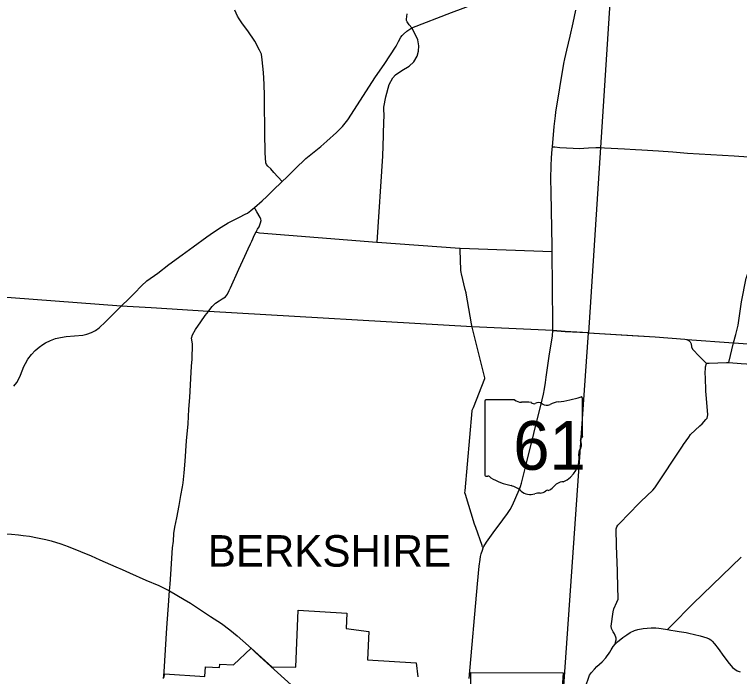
# Model space of a CAD drawing. Extents: x 1729596 to 1925846, y 659247 to 911751.
# Drawn here: x 1855559 to 1876281, y 821273 to 840189 of the extents above; entities that cross this region are included whole.
import ezdxf

# ---------------------------------------------------------------- set-up
doc = ezdxf.new("R2010")
doc.units = 0
for name, color, linetype in [('GM_X_Corporation', 7, 'Continuous'), ('GM_X_County_Road', 7, 'Continuous'), ('GM_X_State_Route', 7, 'Continuous'), ('GM_X_State_Shield', 7, 'Continuous'), ('GM_X_Township', 7, 'Continuous'), ('GM_X_Township_Road', 7, 'Continuous'), ('GM_X_Township_Text', 7, 'Continuous'), ('GM_X_US_Route', 7, 'Continuous')]:
    doc.layers.add(name, color=color, linetype=linetype)

msp = doc.modelspace()

# ---------------------------------------------------------------- linework, layer by layer
at = {"layer": 'GM_X_Corporation'}
for points in [[(1859841, 821244), (1859848, 821345), (1860999, 821277), (1861021, 821551), (1861422, 821527), (1861430, 821628), (1861816, 821605), (1862321, 822084), (1862912, 821546), (1863596, 821544), (1863668, 823164), (1865058, 823080), (1865034, 822645), (1865687, 822560), (1865651, 821750), (1867041, 821665), (1867085, 821260)], [(1868600, 820997), (1868600, 821384), (1871245, 821376), (1871152, 820118)]]:
    msp.add_lwpolyline(points, dxfattribs=at)
at = {"layer": 'GM_X_County_Road'}
for points in [[(1863210, 835416), (1863210, 835416), (1862967, 835675), (1862884, 835775), (1862803, 835851), (1862761, 835902), (1862743, 835950), (1862731, 836098), (1862723, 836235), (1862716, 836815), (1862701, 837711), (1862701, 837868), (1862696, 838200), (1862676, 838527), (1862640, 838898), (1862616, 839053), (1862562, 839171), (1862430, 839430), (1862228, 839726), (1862076, 839926), (1861976, 840068), (1861929, 840138), (1861858, 840312)], [(1870933, 836411), (1871002, 836403), (1871142, 836391), (1871530, 836366), (1871699, 836364), (1871833, 836370), (1871969, 836377), (1872176, 836385), (1872306, 836385), (1872331, 836384)], [(1872331, 836384), (1872418, 836383), (1872993, 836351), (1873307, 836333), (1873487, 836321), (1873966, 836289), (1874379, 836263), (1874795, 836230), (1876128, 836148), (1876819, 836105)], [(1862419, 834675), (1862636, 834868), (1862770, 834990), (1862946, 835159), (1863210, 835416)], [(1861726, 832363), (1861735, 832383), (1861969, 832913), (1862146, 833279), (1862238, 833489), (1862307, 833634), (1862341, 833715), (1862421, 833897), (1862467, 833979), (1862506, 834055), (1862550, 834125), (1862592, 834235), (1862607, 834301), (1862600, 834343), (1862594, 834367), (1862583, 834393), (1862483, 834550), (1862445, 834616), (1862419, 834675)], [(1859988, 823723), (1860006, 823907), (1860023, 824199), (1860075, 824953), (1860102, 825144), (1860114, 825358), (1860137, 825544), (1860198, 825807), (1860261, 826156), (1860312, 826449), (1860361, 826688), (1860376, 826807), (1860409, 827097), (1860434, 827429), (1860477, 828006), (1860520, 828490), (1860543, 828910), (1860568, 829249), (1860600, 829791), (1860621, 830141), (1860638, 830337), (1860634, 830473), (1860648, 830637), (1860646, 830765), (1860638, 830840), (1860616, 830940), (1860643, 831038), (1860729, 831186), (1860886, 831404), (1861011, 831587), (1861106, 831707), (1861116, 831720), (1861213, 831846), (1861306, 831943), (1861407, 832003), (1861491, 832069), (1861588, 832118), (1861646, 832199), (1861699, 832307), (1861726, 832363)], [(1874227, 822615), (1874317, 822710), (1874959, 823358), (1876327, 824682)], [(1872724, 822198), (1872792, 822267), (1872943, 822383), (1873056, 822467), (1873160, 822533), (1873276, 822590), (1873373, 822621), (1873532, 822646), (1873759, 822667), (1873891, 822665), (1873977, 822657), (1874044, 822647), (1874227, 822615), (1874315, 822599), (1874444, 822579), (1874557, 822560), (1874752, 822527), (1874836, 822512), (1875152, 822435), (1875346, 822380), (1875416, 822349), (1875458, 822321), (1875497, 822287), (1875565, 822207), (1875667, 822073), (1875831, 821849), (1875981, 821648), (1876039, 821575), (1876079, 821533), (1876143, 821482), (1876217, 821438), (1876297, 821406)], [(1871742, 820151), (1871742, 820151), (1871754, 820333), (1871771, 820532), (1871780, 820600), (1871796, 820672), (1871893, 821017), (1871942, 821170), (1871996, 821311), (1872051, 821390), (1872132, 821486), (1872206, 821558), (1872281, 821630), (1872352, 821694), (1872457, 821804), (1872502, 821861), (1872537, 821910), (1872571, 821965), (1872610, 822031), (1872673, 822132), (1872724, 822198)]]:
    msp.add_lwpolyline(points, dxfattribs=at)
at = {"layer": 'GM_X_State_Route'}
msp.add_lwpolyline([(1868550, 821219), (1868792, 823921), (1868838, 824429), (1868865, 824617), (1868879, 824699), (1868899, 824776), (1868933, 824884), (1868958, 824946), (1868978, 824987), (1869049, 825113), (1869236, 825376), (1869514, 825748), (1869651, 825934), (1869725, 826044), (1869794, 826172), (1869986, 826604), (1870025, 826707), (1870053, 826795), (1870072, 826869), (1870177, 827297), (1870402, 828215), (1870637, 829183), (1870675, 829343), (1870708, 829497), (1870737, 829677), (1870759, 829830), (1870855, 830493), (1870918, 830884), (1870933, 831006), (1870943, 831158), (1870942, 831364), (1870928, 833417), (1870925, 833572), (1870898, 835100), (1870893, 835500), (1870895, 835861), (1870908, 836093), (1870926, 836338), (1870933, 836411), (1870982, 836992), (1871017, 837298), (1871032, 837400), (1871261, 838785), (1871288, 838923), (1871345, 839169), (1871441, 839565), (1871531, 839946), (1871607, 840316)], dxfattribs=at)
at = {"layer": 'GM_X_State_Shield'}
for p, q in [((1869005, 829143), (1869005, 827030)), ((1869005, 829143), (1869005, 827030)), ((1869848, 829179), (1869032, 829179)), ((1869848, 829179), (1869032, 829179)), ((1871789, 828126), (1871789, 829232)), ((1871789, 828126), (1871789, 829232)), ((1871789, 828127), (1871789, 828126)), ((1871789, 828127), (1871789, 828126))]:
    msp.add_line(p, q, dxfattribs=at)
for centre, radius, start, end in [((1869037, 829147), 32.3, 98.1301, 188.1301), ((1869037, 829147), 32.3, 98.1301, 188.1301), ((1870042, 829425), 313, 231.6195, 271.1119), ((1870042, 829425), 313, 231.6195, 271.1119), ((1870146, 827993), 1123, 80.4867, 94.9883), ((1870146, 827993), 1123, 80.4867, 94.9883), ((1870400, 829158), 90.3, 219.7921, 297.1024), ((1870400, 829158), 90.3, 219.7921, 297.1024), ((1870533, 828914), 188, 54.4667, 119.1411), ((1870533, 828914), 188, 54.4667, 119.1411), ((1871174, 828534), 594, 97.3462, 120.7689), ((1871174, 828534), 594, 97.3462, 120.7689), ((1870797, 832060), 2953, 275.8445, 288.9065), ((1870797, 832060), 2953, 275.8445, 288.9065), ((1871758, 829236), 31, 351.8621, 97.738), ((1871758, 829236), 31, 351.8621, 97.738), ((1870775, 829249), 226, 233.8562, 294.8282), ((1870775, 829249), 226, 233.8562, 294.8282), ((1871782, 828045), 48, 107.944, 210.337), ((1871782, 828045), 48, 107.944, 210.337), ((1871756, 828122), 33.2, 289.6038, 7.7341), ((1871756, 828122), 33.2, 289.6038, 7.7341), ((1871477, 827905), 288, 340.033, 23.6496), ((1871477, 827905), 288, 340.033, 23.6496), ((1870963, 827523), 739, 292.3089, 8.9858), ((1870963, 827523), 739, 292.3089, 8.9858), ((1871900, 827664), 210, 136.8065, 186.9296), ((1871900, 827664), 210, 136.8065, 186.9296), ((1869037, 827025), 32.5, 171.9584, 258.3066), ((1869037, 827025), 32.5, 171.9584, 258.3066), ((1869042, 827241), 248, 267.339, 280.6039), ((1869042, 827241), 248, 267.339, 280.6039), ((1869093, 826908), 89.5, 29.7484, 93.2717), ((1869093, 826908), 89.5, 29.7484, 93.2717), ((1870223, 828806), 2132, 240.4129, 257.1985), ((1870223, 828806), 2132, 240.4129, 257.1985), ((1871274, 826436), 404, 94.4031, 142.5768), ((1871274, 826436), 404, 94.4031, 142.5768), ((1869588, 826080), 667, 47.1842, 75.836), ((1869588, 826080), 667, 47.1842, 75.836), ((1870762, 826825), 239, 282.8732, 323.2771), ((1870762, 826825), 239, 282.8732, 323.2771), ((1870309, 826897), 423, 230.7004, 286.2918), ((1870309, 826897), 423, 230.7004, 286.2918), ((1870554, 826167), 348, 85.6951, 111.2099), ((1870554, 826167), 348, 85.6951, 111.2099), ((1870585, 826739), 226, 268.777, 315.5493), ((1870585, 826739), 226, 268.777, 315.5493), ((1870789, 826534), 63.5, 65.7517, 132.6484), ((1870789, 826534), 63.5, 65.7517, 132.6484)]:
    msp.add_arc(centre, radius, start, end, dxfattribs=at)
at = {"layer": 'GM_X_Township'}
for points in [[(1850615, 859080), (1861827, 858324), (1863977, 858188), (1869100, 857855), (1873671, 857558), (1873447, 853777), (1873266, 851105), (1872889, 845433), (1872874, 845201), (1872678, 842151), (1872497, 839344), (1872306, 836385), (1871965, 831096), (1871301, 831135), (1870943, 831158), (1868637, 831266), (1861106, 831707), (1859467, 831803), (1858606, 831851), (1854821, 832136)], [(1871199, 820179), (1871965, 831096), (1873866, 830983), (1874715, 830911), (1874782, 830900), (1876113, 830808), (1881808, 830417), (1885186, 830186), (1888609, 830001), (1895732, 829600), (1898513, 829466)]]:
    msp.add_lwpolyline(points, dxfattribs=at)
at = {"layer": 'GM_X_Township_Road'}
for points in [[(1866665, 839615), (1866674, 839624), (1866777, 839711), (1866913, 839811), (1868052, 840243), (1868716, 840498), (1869221, 840653), (1869529, 840766), (1869582, 840790), (1869627, 840814), (1869702, 840869), (1869986, 841148), (1870122, 841273), (1870349, 841472), (1870605, 841706), (1870651, 841731), (1870706, 841746), (1870745, 841748), (1871135, 841758), (1871285, 841769), (1871833, 841832), (1871888, 841839)], [(1866913, 839811), (1866844, 839894), (1866779, 839980), (1866764, 840018), (1866765, 840057), (1866786, 840206)], [(1866119, 837164), (1866120, 837249), (1866117, 837540), (1866169, 837838), (1866264, 838193), (1866369, 838375), (1866452, 838465), (1866628, 838586), (1866843, 838716), (1866969, 838837), (1867068, 839000), (1867109, 839145), (1867118, 839292), (1867083, 839467), (1867007, 839630), (1866913, 839811)], [(1863210, 835416), (1863339, 835540), (1863580, 835778), (1863887, 836070), (1864310, 836414), (1864489, 836569), (1864766, 836819), (1864851, 836902), (1864933, 836989), (1865090, 837183), (1865880, 838411), (1866121, 838762), (1866467, 839283), (1866481, 839304), (1866538, 839419), (1866602, 839540), (1866637, 839586), (1866665, 839615)], [(1865920, 833680), (1866088, 836143), (1866109, 836734), (1866119, 837164)], [(1876176, 831049), (1876244, 831313), (1876339, 831976), (1876476, 832658), (1876479, 832675), (1876506, 832758), (1876634, 833154), (1876703, 833255), (1876835, 833358), (1876875, 833401), (1876911, 833448), (1876937, 833491), (1877010, 833643), (1877414, 834454), (1877715, 835018), (1877883, 835308), (1878069, 835602), (1878276, 835912), (1878286, 835945), (1878286, 835969), (1878279, 835990)], [(1858615, 831860), (1858629, 831874), (1858640, 831885), (1858803, 832048), (1858984, 832227), (1859187, 832432), (1859343, 832576), (1859660, 832798), (1859970, 833046), (1860353, 833317), (1860669, 833546), (1861057, 833840), (1861243, 833973), (1861463, 834112), (1861670, 834232), (1861799, 834300), (1861993, 834401), (1862156, 834482), (1862216, 834517), (1862315, 834588), (1862419, 834675)], [(1862467, 833979), (1862487, 833966), (1862562, 833955), (1865917, 833680)], [(1865917, 833680), (1865920, 833680), (1868291, 833514)], [(1868291, 833514), (1868297, 833513), (1870928, 833417)], [(1868631, 831304), (1868622, 831353), (1868468, 832226), (1868466, 832236), (1868443, 832328), (1868331, 832783), (1868323, 832814), (1868320, 832886), (1868299, 833460), (1868297, 833513)], [(1855539, 829573), (1855621, 829675), (1855677, 829764), (1855733, 829882), (1855778, 830005), (1855828, 830130), (1855872, 830221), (1855943, 830341), (1856042, 830473), (1856145, 830584), (1856260, 830683), (1856373, 830763), (1856446, 830807), (1856586, 830875), (1856728, 830927), (1856876, 830964), (1857032, 830986), (1857514, 831030), (1857625, 831055), (1857756, 831102), (1857871, 831163), (1857978, 831239), (1858159, 831407), (1858456, 831698), (1858606, 831851), (1858615, 831860)], [(1868958, 824946), (1868944, 824965), (1868936, 824983), (1868928, 824995), (1868921, 825014), (1868744, 825529), (1868727, 825578), (1868711, 825628), (1868446, 826474), (1868431, 826520), (1868437, 826576), (1868642, 828861), (1868643, 828881), (1868674, 828959), (1868998, 829785), (1869005, 829803), (1868985, 829885), (1868641, 831251), (1868637, 831266), (1868631, 831302), (1868631, 831304)], [(1870943, 831158), (1871301, 831135), (1871925, 831098)], [(1871925, 831098), (1871965, 831096), (1873217, 831021)], [(1873217, 831021), (1873866, 830982), (1874715, 830911), (1874765, 830902)], [(1875972, 830241), (1876113, 830808), (1876176, 831049)], [(1874765, 830902), (1874783, 830900), (1874828, 830878), (1874871, 830836), (1874883, 830819), (1874897, 830780), (1874913, 830695), (1874941, 830628), (1874964, 830595), (1875107, 830442), (1875306, 830250), (1875338, 830221), (1875351, 830222)], [(1872724, 822198), (1872740, 822251), (1872755, 822319), (1872752, 822371), (1872746, 822394), (1872704, 822488), (1872669, 822549), (1872625, 822647), (1872615, 822712), (1872668, 823117), (1872687, 823211), (1872776, 823402), (1872815, 823486), (1872782, 824594), (1872778, 824698), (1872760, 825437), (1872758, 825496), (1872774, 825554), (1872808, 825595), (1872850, 825648), (1873403, 826215), (1873458, 826272), (1873801, 826601), (1873865, 826663), (1874648, 827854), (1874679, 827899), (1874830, 828116), (1874879, 828186), (1875151, 828436), (1875213, 828493), (1875315, 828614), (1875353, 828659), (1875371, 828749), (1875327, 829329), (1875320, 829415), (1875305, 829837), (1875302, 829912), (1875309, 830123), (1875338, 830221)], [(1875351, 830222), (1875410, 830224), (1875906, 830241), (1875972, 830241)], [(1875972, 830241), (1876325, 830221), (1876782, 830190), (1877695, 830124), (1878463, 830066), (1878952, 830045), (1879551, 830034), (1879982, 830022), (1880411, 830048), (1880624, 830061), (1881052, 830089), (1881159, 830094)], [(1859818, 821219), (1859833, 821406), (1859916, 822663), (1859971, 823438), (1859983, 823596), (1859988, 823723)]]:
    msp.add_lwpolyline(points, dxfattribs=at)
at = {"layer": 'GM_X_US_Route'}
for points in [[(1855037, 825370), (1855173, 825360), (1855248, 825354), (1855476, 825337), (1855674, 825320), (1855808, 825306), (1855988, 825281), (1856219, 825240), (1856454, 825186), (1856610, 825146), (1856879, 825067), (1857093, 824992), (1857448, 824848), (1857746, 824717), (1857872, 824661)], [(1857872, 824661), (1858002, 824603), (1858452, 824407), (1858634, 824327), (1858849, 824233), (1859315, 824029), (1859681, 823869), (1859988, 823723), (1860406, 823477), (1860588, 823365), (1860963, 823124), (1861157, 822990), (1861474, 822783), (1861713, 822608), (1861927, 822435), (1862088, 822291), (1862329, 822071), (1862359, 822043)], [(1862359, 822043), (1862416, 821990), (1862570, 821847), (1862984, 821471)], [(1862984, 821471), (1864255, 820317), (1864708, 819903), (1864947, 819685), (1865843, 818874), (1866225, 818531)]]:
    msp.add_lwpolyline(points, dxfattribs=at)

# ---------------------------------------------------------------- texts
at = {"layer": 'GM_X_State_Shield'}
msp.add_text('61', height=1392.2, dxfattribs=at).set_placement((1869815, 827179))
msp.add_text('61', height=1392.2, dxfattribs=at).set_placement((1869815, 827179))
at = {"layer": 'GM_X_Township_Text'}
msp.add_text('BERKSHIRE', height=900, rotation=0, dxfattribs=at).set_placement((1861082, 824412))

doc.saveas('drawing.dxf')
